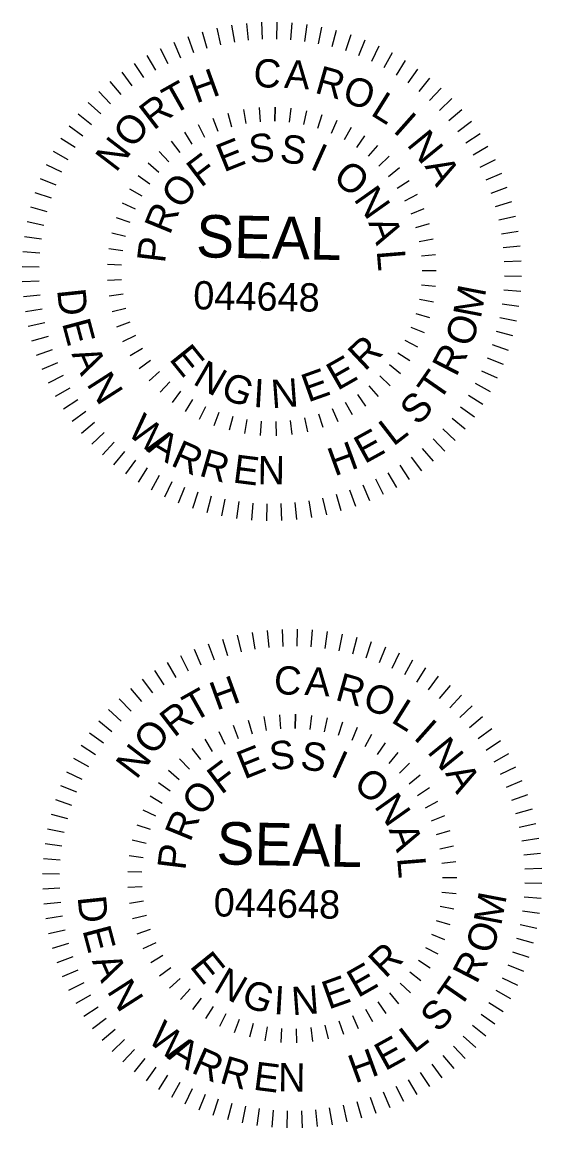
# Model space of a CAD drawing. Extents: x 0 to 2694, y -1 to 1501.
# Drawn here: x 3.6853 to 3.812, y 1.3954 to 1.6653 of the extents above; entities that cross this region are included whole.
import ezdxf

# ---------------------------------------------------------------- set-up
doc = ezdxf.new("R2010")
doc.units = 0
doc.layers.add('Aband Utility MH (M2) CELL', color=7, linetype='Continuous')

msp = doc.modelspace()

# ---------------------------------------------------------------- linework, layer by layer
at = {"layer": 'Aband Utility MH (M2) CELL'}
for p, q in [((3.74738, 1.66527), (3.7473, 1.66112)), ((3.72922, 1.66288), (3.73037, 1.65888)), ((3.73279, 1.66379), (3.73369, 1.65974)), ((3.73639, 1.66449), (3.73706, 1.6604)), ((3.74004, 1.66497), (3.74045, 1.66085)), ((3.7437, 1.66523), (3.74387, 1.66109)), ((3.75106, 1.66508), (3.75073, 1.66095)), ((3.75471, 1.66468), (3.75413, 1.66057)), ((3.75833, 1.66406), (3.7575, 1.65999)), ((3.76191, 1.66322), (3.76084, 1.65921)), ((3.7223, 1.6604), (3.72392, 1.65659)), ((3.72572, 1.66175), (3.72712, 1.65783)), ((3.76544, 1.66216), (3.76412, 1.65822)), ((3.76888, 1.66089), (3.76733, 1.65704)), ((3.71896, 1.65886), (3.72082, 1.65515)), ((3.77225, 1.65941), (3.77048, 1.65566)), ((3.77552, 1.65774), (3.77352, 1.6541)), ((3.7126, 1.65518), (3.71489, 1.65172)), ((3.71572, 1.65712), (3.7178, 1.65353)), ((3.77869, 1.65587), (3.77647, 1.65236)), ((3.7096, 1.65306), (3.71209, 1.64975)), ((3.78174, 1.65381), (3.77931, 1.65045)), ((3.70672, 1.65076), (3.70941, 1.64761)), ((3.78465, 1.65158), (3.78203, 1.64836)), ((3.78743, 1.64916), (3.78462, 1.64612)), ((3.704, 1.6483), (3.70687, 1.64531)), ((3.79006, 1.64659), (3.78707, 1.64372)), ((3.70143, 1.64567), (3.70447, 1.64286)), ((3.73925, 1.64393), (3.73984, 1.64052)), ((3.74309, 1.64441), (3.74336, 1.64097)), ((3.74697, 1.64452), (3.7469, 1.64107)), ((3.7469, 1.64107), (3.74697, 1.64452)), ((3.75084, 1.64426), (3.75044, 1.64083)), ((3.79252, 1.64387), (3.78937, 1.64118)), ((3.69901, 1.64289), (3.70223, 1.64027)), ((3.73179, 1.64186), (3.73303, 1.63863)), ((3.73547, 1.64308), (3.73639, 1.63974)), ((3.75466, 1.64362), (3.75393, 1.64024)), ((3.7584, 1.64262), (3.75735, 1.63933)), ((3.76204, 1.64127), (3.76067, 1.63809)), ((3.79483, 1.64099), (3.79151, 1.6385)), ((3.69678, 1.63998), (3.70014, 1.63755)), ((3.72486, 1.6384), (3.7267, 1.63547)), ((3.72824, 1.6403), (3.72978, 1.63721)), ((3.76552, 1.63956), (3.76386, 1.63653)), ((3.69472, 1.63693), (3.69823, 1.63471)), ((3.72168, 1.63618), (3.72379, 1.63344)), ((3.76882, 1.63753), (3.76687, 1.63467)), ((3.79694, 1.63799), (3.79349, 1.6357)), ((3.69285, 1.63376), (3.69649, 1.63176)), ((3.71873, 1.63367), (3.7211, 1.63115)), ((3.77191, 1.63519), (3.76969, 1.63253)), ((3.79888, 1.63487), (3.79529, 1.63279)), ((3.69118, 1.63049), (3.69493, 1.62871)), ((3.71603, 1.63089), (3.71863, 1.62861)), ((3.77476, 1.63256), (3.77229, 1.63013)), ((3.80062, 1.63163), (3.79691, 1.62977)), ((3.71362, 1.62786), (3.71642, 1.62583)), ((3.77734, 1.62967), (3.77466, 1.6275)), ((3.80216, 1.62829), (3.79835, 1.62667)), ((3.6897, 1.62712), (3.69355, 1.62557)), ((3.77964, 1.62655), (3.77675, 1.62463)), ((3.80351, 1.62487), (3.7996, 1.62347)), ((3.68843, 1.62367), (3.69237, 1.62236)), ((3.71151, 1.62461), (3.71449, 1.62286)), ((3.78161, 1.62322), (3.77856, 1.62159)), ((3.68737, 1.62015), (3.69138, 1.61908)), ((3.70972, 1.62116), (3.71286, 1.61972)), ((3.78327, 1.6197), (3.78007, 1.61839)), ((3.80464, 1.62137), (3.80065, 1.62022)), ((3.70828, 1.61756), (3.71155, 1.61643)), ((3.80555, 1.6178), (3.80151, 1.6169)), ((3.68653, 1.61657), (3.6906, 1.61574)), ((3.78457, 1.61605), (3.78125, 1.61505)), ((3.80625, 1.6142), (3.80216, 1.61353)), ((3.68591, 1.61295), (3.69002, 1.61237)), ((3.70718, 1.61385), (3.71054, 1.61303)), ((3.78551, 1.61229), (3.78212, 1.61162)), ((3.68551, 1.60929), (3.68964, 1.60896)), ((3.70646, 1.61004), (3.70988, 1.60956)), ((3.80673, 1.61055), (3.80261, 1.61014)), ((3.7061, 1.60618), (3.70955, 1.60602)), ((3.74334, 1.60681), (3.74334, 1.60681)), ((3.78609, 1.60846), (3.78265, 1.60812)), ((3.80699, 1.60689), (3.80285, 1.60672)), ((3.68532, 1.60562), (3.68947, 1.60554)), ((3.78629, 1.60459), (3.78284, 1.60457)), ((3.80703, 1.60321), (3.80288, 1.60329)), ((3.68536, 1.60194), (3.6895, 1.60211)), ((3.70611, 1.6023), (3.70956, 1.60248)), ((3.78612, 1.60072), (3.78268, 1.60103)), ((3.68562, 1.59828), (3.68974, 1.59869)), ((3.70651, 1.59845), (3.70992, 1.59896)), ((3.80685, 1.59953), (3.80271, 1.59986)), ((3.6861, 1.59463), (3.69019, 1.5953)), ((3.70727, 1.59464), (3.71062, 1.59548)), ((3.7822, 1.59765), (3.7856, 1.59701)), ((3.80644, 1.59588), (3.80234, 1.59646)), ((3.78467, 1.59311), (3.78135, 1.59408)), ((3.80582, 1.59226), (3.80175, 1.59309)), ((3.6868, 1.59103), (3.69085, 1.59193)), ((3.70839, 1.59093), (3.71165, 1.59209)), ((3.7834, 1.58945), (3.78019, 1.59073)), ((3.80498, 1.58868), (3.80097, 1.58975)), ((3.68771, 1.58746), (3.69171, 1.58861)), ((3.70987, 1.58735), (3.713, 1.58883)), ((3.78177, 1.58593), (3.77871, 1.58752)), ((3.68884, 1.58396), (3.69276, 1.58536)), ((3.71168, 1.58393), (3.71466, 1.58569)), ((3.77983, 1.58258), (3.77693, 1.58446)), ((3.80392, 1.58515), (3.79998, 1.58647)), ((3.69019, 1.58054), (3.694, 1.58216)), ((3.71382, 1.58069), (3.71661, 1.58274)), ((3.77756, 1.57943), (3.77486, 1.58158)), ((3.80265, 1.58171), (3.7988, 1.58326)), ((3.69173, 1.5772), (3.69544, 1.57906)), ((3.71627, 1.57768), (3.71884, 1.57998)), ((3.775, 1.57652), (3.77252, 1.57892)), ((3.80117, 1.57834), (3.79742, 1.58011)), ((3.71898, 1.57492), (3.72133, 1.57746)), ((3.77218, 1.57387), (3.76994, 1.5765)), ((3.7995, 1.57507), (3.79586, 1.57707)), ((3.69347, 1.57396), (3.69706, 1.57604)), ((3.72196, 1.57244), (3.72404, 1.57519)), ((3.76911, 1.5715), (3.76713, 1.57434)), ((3.79763, 1.5719), (3.79413, 1.57412)), ((3.69541, 1.57084), (3.69887, 1.57312)), ((3.72515, 1.57025), (3.72697, 1.57319)), ((3.72856, 1.56838), (3.73007, 1.57149)), ((3.76235, 1.56771), (3.76096, 1.57087)), ((3.76583, 1.56944), (3.76413, 1.57246)), ((3.79557, 1.56885), (3.79221, 1.57128)), ((3.69753, 1.56784), (3.70084, 1.57033)), ((3.73212, 1.56684), (3.73333, 1.57008)), ((3.73668, 1.56901), (3.73578, 1.56566)), ((3.7396, 1.56484), (3.74016, 1.56825)), ((3.755, 1.56528), (3.75424, 1.56866)), ((3.75873, 1.56631), (3.75765, 1.5696)), ((3.79334, 1.56594), (3.79012, 1.56856)), ((3.69983, 1.56496), (3.70298, 1.56765)), ((3.74344, 1.56439), (3.74368, 1.56784)), ((3.74732, 1.56431), (3.74722, 1.56777)), ((3.75118, 1.56461), (3.75075, 1.56804)), ((3.79092, 1.56316), (3.78788, 1.56597)), ((3.70229, 1.56224), (3.70528, 1.56511)), ((3.70492, 1.55966), (3.70773, 1.56271)), ((3.78835, 1.56053), (3.78548, 1.56352)), ((3.7077, 1.55725), (3.71032, 1.56047)), ((3.78563, 1.55807), (3.78294, 1.56122)), ((3.71061, 1.55502), (3.71304, 1.55838)), ((3.78275, 1.55577), (3.78026, 1.55908)), ((3.71366, 1.55296), (3.71588, 1.55646)), ((3.71683, 1.55109), (3.71883, 1.55473)), ((3.77663, 1.55171), (3.77455, 1.5553)), ((3.77975, 1.55365), (3.77747, 1.5571)), ((3.7201, 1.54942), (3.72188, 1.55317)), ((3.77005, 1.54843), (3.76843, 1.55224)), ((3.77339, 1.54997), (3.77153, 1.55368)), ((3.72347, 1.54794), (3.72502, 1.55179)), ((3.72692, 1.54667), (3.72823, 1.55061)), ((3.73044, 1.54561), (3.73151, 1.54962)), ((3.76313, 1.54595), (3.76198, 1.54994)), ((3.76663, 1.54708), (3.76523, 1.55099)), ((3.73402, 1.54477), (3.73485, 1.54884)), ((3.73764, 1.54415), (3.73822, 1.54825)), ((3.7413, 1.54374), (3.74163, 1.54788)), ((3.74497, 1.54356), (3.74505, 1.54771)), ((3.74865, 1.5436), (3.74848, 1.54774)), ((3.75231, 1.54386), (3.7519, 1.54798)), ((3.75596, 1.54434), (3.75529, 1.54843)), ((3.75957, 1.54504), (3.75866, 1.54908)), ((3.74869, 1.51705), (3.74885, 1.5129)), ((3.75237, 1.51709), (3.75228, 1.51294)), ((3.75604, 1.5169), (3.75571, 1.51277)), ((3.7342, 1.51469), (3.73536, 1.5107)), ((3.73777, 1.51561), (3.73868, 1.51156)), ((3.74138, 1.51631), (3.74204, 1.51222)), ((3.74502, 1.51679), (3.74544, 1.51266)), ((3.75969, 1.5165), (3.75912, 1.51239)), ((3.76332, 1.51588), (3.76249, 1.51181)), ((3.76689, 1.51503), (3.76583, 1.51102)), ((3.72729, 1.51222), (3.72891, 1.5084)), ((3.73071, 1.51356), (3.73211, 1.50965)), ((3.77042, 1.51398), (3.76911, 1.51003)), ((3.77387, 1.51271), (3.77232, 1.50886)), ((3.72071, 1.50893), (3.72279, 1.50534)), ((3.72395, 1.51068), (3.7258, 1.50696)), ((3.77723, 1.51123), (3.77546, 1.50748)), ((3.78051, 1.50956), (3.77851, 1.50592)), ((3.71758, 1.507), (3.71987, 1.50354)), ((3.78368, 1.50769), (3.78146, 1.50418)), ((3.71458, 1.50488), (3.71707, 1.50157)), ((3.78672, 1.50563), (3.7843, 1.50226)), ((3.78964, 1.50339), (3.78702, 1.50018)), ((3.71171, 1.50258), (3.7144, 1.49942)), ((3.79242, 1.50098), (3.78961, 1.49793)), ((3.70898, 1.50011), (3.71186, 1.49712)), ((3.79504, 1.49841), (3.79205, 1.49554)), ((3.70641, 1.49749), (3.70946, 1.49468)), ((3.74424, 1.49575), (3.74483, 1.49234)), ((3.74808, 1.49623), (3.74834, 1.49278)), ((3.75196, 1.49634), (3.75189, 1.49289)), ((3.75189, 1.49289), (3.75196, 1.49634)), ((3.75583, 1.49607), (3.75542, 1.49264)), ((3.75965, 1.49544), (3.75892, 1.49206)), ((3.79751, 1.49568), (3.79435, 1.493)), ((3.704, 1.49471), (3.70721, 1.49209)), ((3.73677, 1.49368), (3.73801, 1.49045)), ((3.74046, 1.4949), (3.74138, 1.49156)), ((3.76339, 1.49444), (3.76234, 1.49114)), ((3.76702, 1.49308), (3.76566, 1.4899)), ((3.79981, 1.49281), (3.79649, 1.49032)), ((3.70176, 1.4918), (3.70513, 1.48937)), ((3.72984, 1.49022), (3.73168, 1.48728)), ((3.73323, 1.49212), (3.73477, 1.48902)), ((3.7705, 1.49138), (3.76884, 1.48835)), ((3.80193, 1.48981), (3.79847, 1.48752)), ((3.69971, 1.48875), (3.70321, 1.48653)), ((3.72666, 1.488), (3.72878, 1.48526)), ((3.77381, 1.48935), (3.77186, 1.48649)), ((3.69783, 1.48558), (3.70147, 1.48358)), ((3.72371, 1.48549), (3.72608, 1.48296)), ((3.7769, 1.48701), (3.77468, 1.48435)), ((3.80386, 1.48669), (3.80027, 1.4846)), ((3.69617, 1.4823), (3.69991, 1.48053)), ((3.72102, 1.4827), (3.72361, 1.48042)), ((3.77974, 1.48438), (3.77728, 1.48195)), ((3.80561, 1.48344), (3.80189, 1.48159)), ((3.7186, 1.47967), (3.72141, 1.47765)), ((3.78233, 1.48149), (3.77964, 1.47931)), ((3.80715, 1.48011), (3.80333, 1.47848)), ((3.69468, 1.47894), (3.69854, 1.47739)), ((3.7165, 1.47642), (3.71948, 1.47467)), ((3.78462, 1.47836), (3.78174, 1.47645)), ((3.80849, 1.47668), (3.80458, 1.47529)), ((3.69342, 1.47549), (3.69736, 1.47418)), ((3.7866, 1.47503), (3.78355, 1.47341)), ((3.69236, 1.47196), (3.69637, 1.4709)), ((3.71471, 1.47298), (3.71785, 1.47154)), ((3.78825, 1.47152), (3.78505, 1.4702)), ((3.80962, 1.47319), (3.80563, 1.47203)), ((3.69152, 1.46839), (3.69558, 1.46756)), ((3.71326, 1.46938), (3.71653, 1.46825)), ((3.81054, 1.46962), (3.80649, 1.46872)), ((3.71217, 1.46566), (3.71553, 1.46485)), ((3.78955, 1.46787), (3.78624, 1.46687)), ((3.81124, 1.46601), (3.80714, 1.46535)), ((3.6909, 1.46476), (3.695, 1.46419)), ((3.7905, 1.46411), (3.78711, 1.46343)), ((3.69049, 1.46111), (3.69462, 1.46078)), ((3.71144, 1.46185), (3.71486, 1.46138)), ((3.79107, 1.46028), (3.78764, 1.45993)), ((3.81172, 1.46237), (3.80759, 1.46195)), ((3.69031, 1.45744), (3.69445, 1.45736)), ((3.71108, 1.45799), (3.71453, 1.45784)), ((3.74833, 1.45863), (3.74833, 1.45863)), ((3.81198, 1.4587), (3.80783, 1.45854)), ((3.79128, 1.45641), (3.78782, 1.45639)), ((3.81202, 1.45503), (3.80787, 1.45511)), ((3.69034, 1.45376), (3.69449, 1.45393)), ((3.7111, 1.45412), (3.71455, 1.4543)), ((3.79111, 1.45253), (3.78767, 1.45285)), ((3.69061, 1.45009), (3.69473, 1.45051)), ((3.71149, 1.45026), (3.71491, 1.45078)), ((3.78719, 1.44947), (3.79059, 1.44882)), ((3.81183, 1.45135), (3.8077, 1.45168)), ((3.69108, 1.44645), (3.69518, 1.44711)), ((3.71225, 1.44646), (3.7156, 1.4473)), ((3.81142, 1.4477), (3.80732, 1.44828)), ((3.78965, 1.44492), (3.78634, 1.4459)), ((3.8108, 1.44408), (3.80674, 1.4449)), ((3.69178, 1.44284), (3.69583, 1.44375)), ((3.71338, 1.44275), (3.71663, 1.44391)), ((3.78838, 1.44126), (3.78517, 1.44255)), ((3.80996, 1.4405), (3.80595, 1.44157)), ((3.6927, 1.43928), (3.69669, 1.44043)), ((3.71486, 1.43917), (3.71798, 1.44064)), ((3.78676, 1.43775), (3.7837, 1.43934)), ((3.69383, 1.43578), (3.69774, 1.43718)), ((3.71667, 1.43575), (3.71964, 1.43751)), ((3.78482, 1.4344), (3.78191, 1.43627)), ((3.80891, 1.43697), (3.80496, 1.43829)), ((3.69518, 1.43236), (3.69899, 1.43398)), ((3.71881, 1.43251), (3.7216, 1.43455)), ((3.78255, 1.43124), (3.77984, 1.4334)), ((3.80764, 1.43353), (3.80378, 1.43508)), ((3.69671, 1.42902), (3.70043, 1.43087)), ((3.72125, 1.4295), (3.72383, 1.4318)), ((3.77999, 1.42834), (3.77751, 1.43074)), ((3.80616, 1.43016), (3.80241, 1.43193)), ((3.69846, 1.42578), (3.70205, 1.42786)), ((3.72396, 1.42674), (3.72631, 1.42928)), ((3.77717, 1.42568), (3.77492, 1.42832)), ((3.80449, 1.42688), (3.80085, 1.42888)), ((3.72694, 1.42425), (3.72903, 1.42701)), ((3.77409, 1.42332), (3.77212, 1.42615)), ((3.80262, 1.42371), (3.79911, 1.42594)), ((3.70039, 1.42265), (3.70385, 1.42494)), ((3.73014, 1.42206), (3.73196, 1.42501)), ((3.73354, 1.4202), (3.73506, 1.4233)), ((3.76734, 1.41953), (3.76595, 1.42269)), ((3.77081, 1.42126), (3.76911, 1.42427)), ((3.80056, 1.42067), (3.79719, 1.42309)), ((3.70251, 1.41965), (3.70583, 1.42214)), ((3.7371, 1.41866), (3.73832, 1.4219)), ((3.74166, 1.42082), (3.74077, 1.41748)), ((3.74458, 1.41666), (3.74515, 1.42007)), ((3.74843, 1.41621), (3.74866, 1.41966)), ((3.75617, 1.41643), (3.75574, 1.41986)), ((3.75999, 1.4171), (3.75922, 1.42048)), ((3.76372, 1.41813), (3.76264, 1.42142)), ((3.79832, 1.41776), (3.79511, 1.42037)), ((3.70481, 1.41678), (3.70797, 1.41947)), ((3.7523, 1.41613), (3.75221, 1.41959)), ((3.79591, 1.41497), (3.79286, 1.41779)), ((3.70728, 1.41406), (3.71027, 1.41693)), ((3.7099, 1.41148), (3.71272, 1.41453)), ((3.79334, 1.41235), (3.79046, 1.41534)), ((3.71268, 1.40907), (3.7153, 1.41228)), ((3.79061, 1.40988), (3.78792, 1.41304)), ((3.7156, 1.40683), (3.71802, 1.4102)), ((3.78474, 1.40546), (3.78245, 1.40892)), ((3.78774, 1.40758), (3.78525, 1.4109)), ((3.71864, 1.40478), (3.72086, 1.40828)), ((3.72181, 1.40291), (3.72381, 1.40654)), ((3.78161, 1.40353), (3.77953, 1.40712)), ((3.72509, 1.40124), (3.72686, 1.40498)), ((3.72845, 1.39976), (3.73001, 1.40361)), ((3.77503, 1.40025), (3.77341, 1.40406)), ((3.77837, 1.40178), (3.77652, 1.4055)), ((3.7319, 1.39849), (3.73321, 1.40243)), ((3.73543, 1.39743), (3.73649, 1.40144)), ((3.76455, 1.39685), (3.76364, 1.4009)), ((3.76812, 1.39777), (3.76696, 1.40176)), ((3.77161, 1.3989), (3.77021, 1.40281)), ((3.73901, 1.39659), (3.73983, 1.40065)), ((3.74263, 1.39597), (3.74321, 1.40007)), ((3.74628, 1.39556), (3.74661, 1.3997)), ((3.74995, 1.39538), (3.75004, 1.39953)), ((3.75363, 1.39542), (3.75347, 1.39956)), ((3.7573, 1.39568), (3.75688, 1.3998)), ((3.76094, 1.39615), (3.76028, 1.40025))]:
    msp.add_line(p, q, dxfattribs=at)

# ---------------------------------------------------------------- texts
for s, height, rotation, p in [('C', 0.00691, 356.2217, (3.74154, 1.64954)), ('A', 0.00691, 356.2217, (3.74909, 1.64925)), ('R', 0.00691, 344.2124, (3.75639, 1.64809)), ('H', 0.00691, 19.9324, (3.72771, 1.64537)), ('O', 0.00691, 341.1556, (3.76304, 1.64597)), ('T', 0.00691, 29.3644, (3.72208, 1.64248)), ('R', 0.00691, 37.5253, (3.71736, 1.6387)), ('L', 0.00691, 328.0193, (3.77001, 1.64275)), ('O', 0.00691, 50.5821, (3.71227, 1.63415)), ('I', 0.00691, 318.4439, (3.7755, 1.63863)), ('N', 0.00691, 309.1494, (3.77889, 1.63531)), ('N', 0.00691, 52.5415, (3.70818, 1.62839)), ('E', 0.00691, 21.8091, (3.73446, 1.62855)), ('S', 0.00691, 6.5129, (3.741, 1.63079)), ('S', 0.00691, 351.2166, (3.74791, 1.63123)), ('I', 0.00691, 335.9204, (3.75522, 1.62959)), ('F', 0.00691, 37.1054, (3.72886, 1.62475)), ('O', 0.00691, 320.6242, (3.76074, 1.62679)), ('A', 0.00691, 299.3819, (3.78335, 1.63012)), ('O', 0.00691, 52.4016, (3.72415, 1.61927)), ('N', 0.00691, 305.3279, (3.76597, 1.62206)), ('R', 0.00691, 67.6979, (3.7213, 1.61312)), ('SEAL', 0.010372, 358.8648, (3.72766, 1.60789)), ('A', 0.00691, 290.0317, (3.76965, 1.61633)), ('P', 0.00691, 82.9941, (3.72012, 1.60629)), ('L', 0.00691, 274.7354, (3.77175, 1.60945)), ('044648', 0.006909, 358.8648, (3.72698, 1.59519)), ('M', 0.00691, 79.1773, (3.7971, 1.59272)), ('D', 0.00691, 275.9811, (3.69383, 1.59991)), ('E', 0.00691, 284.9836, (3.69499, 1.59181)), ('O', 0.00691, 71.1829, (3.79472, 1.58569)), ('R', 0.00691, 43.4297, (3.76884, 1.57988)), ('A', 0.00691, 293.8062, (3.69729, 1.58429)), ('E', 0.00691, 308.9349, (3.72098, 1.58297)), ('R', 0.00691, 62.7337, (3.79111, 1.57847)), ('N', 0.00691, 329.7899, (3.72667, 1.57709)), ('E', 0.00691, 29.6586, (3.76216, 1.5752)), ('N', 0.00691, 302.6889, (3.70085, 1.57695)), ('G', 0.00691, 338.5562, (3.73337, 1.57372)), ('E', 0.00691, 19.6727, (3.75501, 1.57239)), ('T', 0.00691, 55.228, (3.78693, 1.57238)), ('I', 0.00691, 356.651, (3.74155, 1.57135)), ('N', 0.00691, 4.2806, (3.74623, 1.57102)), ('S', 0.00691, 46.5552, (3.78179, 1.56658)), ('W', 0.00691, 320.3641, (3.71061, 1.56485)), ('E', 0.00691, 28.88, (3.76879, 1.55734)), ('L', 0.00691, 37.7626, (3.7758, 1.56158)), ('A', 0.00691, 329.3125, (3.71556, 1.56059)), ('R', 0.00691, 336.0279, (3.72128, 1.55716)), ('H', 0.00691, 19.9974, (3.76146, 1.55436)), ('R', 0.00691, 343.8077, (3.7282, 1.55463)), ('E', 0.00691, 352.7158, (3.73649, 1.55292)), ('N', 0.00691, 359.3001, (3.74269, 1.55249)), ('C', 0.00691, 356.2217, (3.74653, 1.50136)), ('A', 0.00691, 356.2217, (3.75407, 1.50107)), ('R', 0.00691, 344.2124, (3.76137, 1.49991)), ('H', 0.00691, 19.9324, (3.73269, 1.49719)), ('O', 0.00691, 341.1556, (3.76802, 1.49779)), ('T', 0.00691, 29.3644, (3.72707, 1.49429)), ('R', 0.00691, 37.5253, (3.72235, 1.49052)), ('L', 0.00691, 328.0193, (3.77499, 1.49457)), ('O', 0.00691, 50.5821, (3.71725, 1.48597)), ('I', 0.00691, 318.4439, (3.78048, 1.49045)), ('S', 0.00691, 6.5129, (3.74598, 1.48261)), ('N', 0.00691, 309.1494, (3.78388, 1.48712)), ('N', 0.00691, 52.5415, (3.71317, 1.48021)), ('E', 0.00691, 21.8091, (3.73945, 1.48037)), ('S', 0.00691, 351.2166, (3.75289, 1.48305)), ('I', 0.00691, 335.9204, (3.76021, 1.48141)), ('F', 0.00691, 37.1054, (3.73384, 1.47657)), ('O', 0.00691, 320.6242, (3.76572, 1.47861)), ('A', 0.00691, 299.3819, (3.78834, 1.48193)), ('O', 0.00691, 52.4016, (3.72914, 1.47109)), ('N', 0.00691, 305.3279, (3.77095, 1.47388)), ('R', 0.00691, 67.6979, (3.72628, 1.46494)), ('SEAL', 0.010372, 358.8648, (3.73264, 1.45971)), ('A', 0.00691, 290.0317, (3.77463, 1.46815)), ('P', 0.00691, 82.9941, (3.7251, 1.45811)), ('L', 0.00691, 274.7354, (3.77673, 1.46126)), ('044648', 0.006909, 358.8648, (3.73196, 1.44701)), ('M', 0.00691, 79.1773, (3.80208, 1.44454)), ('D', 0.00691, 275.9811, (3.69882, 1.45173)), ('E', 0.00691, 284.9836, (3.69998, 1.44363)), ('O', 0.00691, 71.1829, (3.7997, 1.43751)), ('E', 0.00691, 308.9349, (3.72597, 1.43478)), ('R', 0.00691, 43.4297, (3.77382, 1.4317)), ('A', 0.00691, 293.8062, (3.70227, 1.43611)), ('R', 0.00691, 62.7337, (3.79609, 1.43028)), ('N', 0.00691, 329.7899, (3.73166, 1.42891)), ('E', 0.00691, 29.6586, (3.76715, 1.42701)), ('N', 0.00691, 302.6889, (3.70583, 1.42877)), ('G', 0.00691, 338.5562, (3.73835, 1.42554)), ('E', 0.00691, 19.6727, (3.76, 1.42421)), ('T', 0.00691, 55.228, (3.79192, 1.4242)), ('I', 0.00691, 356.651, (3.74654, 1.42316)), ('N', 0.00691, 4.2806, (3.75122, 1.42284)), ('S', 0.00691, 46.5552, (3.78678, 1.4184)), ('W', 0.00691, 320.3641, (3.71559, 1.41667)), ('L', 0.00691, 37.7626, (3.78079, 1.41339)), ('A', 0.00691, 329.3125, (3.72054, 1.41241)), ('E', 0.00691, 28.88, (3.77378, 1.40916)), ('R', 0.00691, 336.0279, (3.72627, 1.40898)), ('H', 0.00691, 19.9974, (3.76645, 1.40618)), ('R', 0.00691, 343.8077, (3.73319, 1.40645)), ('E', 0.00691, 352.7158, (3.74148, 1.40473)), ('N', 0.00691, 359.3001, (3.74768, 1.4043))]:
    msp.add_text(s, height=height, rotation=rotation, dxfattribs=at).set_placement(p)

doc.saveas('drawing.dxf')
